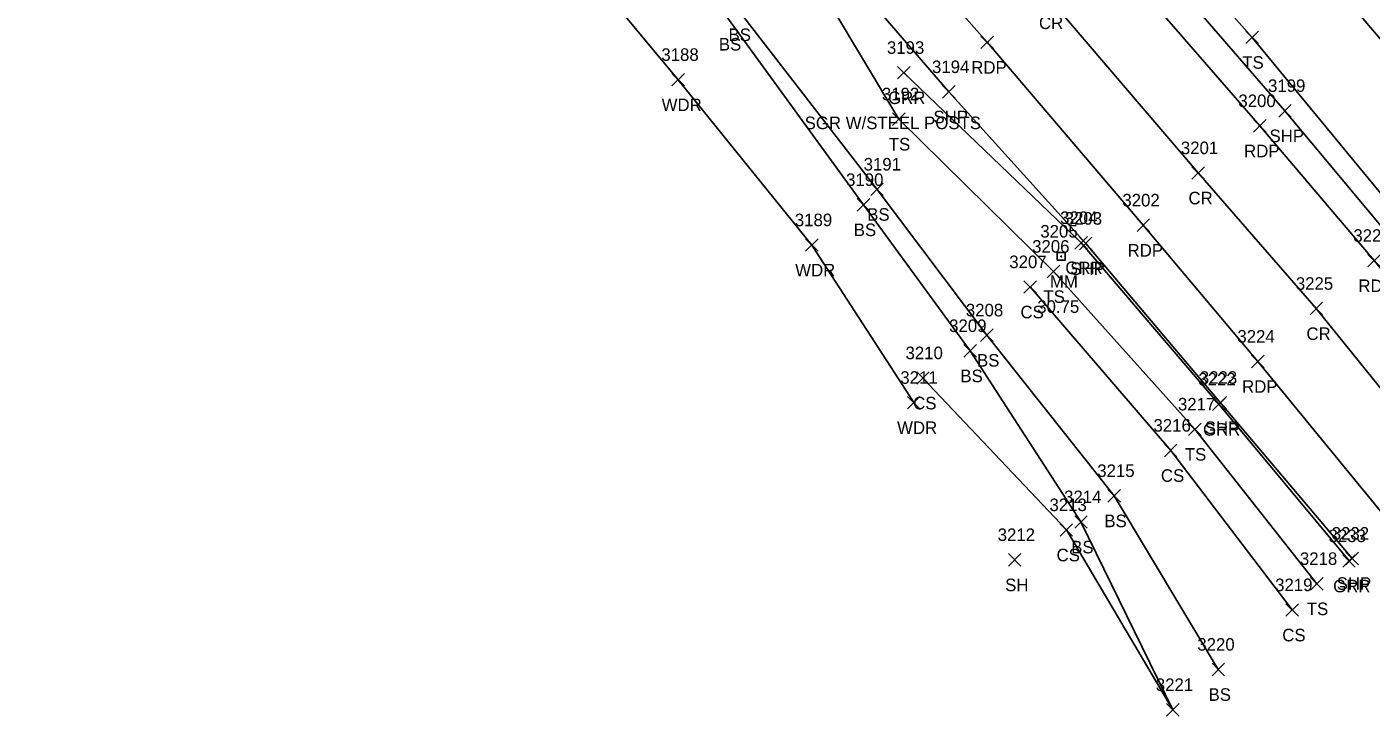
# Model space of a CAD drawing. Extents: x 1647574 to 1652703, y 212895 to 228670.
# Drawn here: x 1649906.5 to 1650120.6, y 225938.9 to 226048.7 of the extents above; entities that cross this region are included whole.
import ezdxf

# ---------------------------------------------------------------- set-up
doc = ezdxf.new("R2010")
doc.units = 0
for name, color, linetype in [('L_A', 7, 'Continuous'), ('L_I', 7, 'Continuous'), ('L_TIC', 7, 'Continuous'), ('LAWA', 7, 'Continuous'), ('LELB', 7, 'Continuous'), ('P_A', 7, 'Continuous'), ('P_I', 7, 'Continuous'), ('P_TIC', 7, 'Continuous'), ('PET', 7, 'Continuous'), ('PRC', 7, 'Continuous'), ('PSP', 7, 'Continuous'), ('R_A', 7, 'Continuous'), ('R_C', 7, 'Continuous'), ('R_I', 7, 'Continuous'), ('R_TIC', 7, 'Continuous'), ('RGR', 7, 'Continuous'), ('S_A', 7, 'Continuous'), ('S_C', 7, 'Continuous'), ('S_I', 7, 'Continuous'), ('SRM', 7, 'Continuous')]:
    doc.layers.add(name, color=color, linetype=linetype)

msp = doc.modelspace()

# ---------------------------------------------------------------- linework, layer by layer
at = {"layer": 'L_TIC'}
for points in [[(1650100.66, 226046.08), (1650102.66, 226048.08)], [(1650102.66, 226046.08), (1650100.66, 226048.08)], [(1650009.23, 226039.33), (1650011.23, 226041.33)], [(1650011.23, 226039.33), (1650009.23, 226041.33)], [(1650044.36, 226033.05), (1650046.36, 226035.05)], [(1650046.36, 226033.05), (1650044.36, 226035.05)], [(1650040.89, 226021.86), (1650042.89, 226023.86)], [(1650042.89, 226021.86), (1650040.89, 226023.86)], [(1650038.74, 226019.41), (1650040.74, 226021.41)], [(1650040.74, 226019.41), (1650038.74, 226021.41)], [(1650030.5, 226012.99), (1650032.5, 226014.99)], [(1650032.5, 226012.99), (1650030.5, 226014.99)], [(1650068.99, 226008.77), (1650070.99, 226010.77)], [(1650070.99, 226008.77), (1650068.99, 226010.77)], [(1650065.29, 226006.31), (1650067.29, 226008.31)], [(1650067.29, 226006.31), (1650065.29, 226008.31)], [(1650058.37, 225998.62), (1650060.37, 226000.62)], [(1650060.37, 225998.62), (1650058.37, 226000.62)], [(1650055.73, 225996.13), (1650057.73, 225998.13)], [(1650057.73, 225996.13), (1650055.73, 225998.13)], [(1650048.21, 225991.8), (1650050.21, 225993.8)], [(1650050.21, 225991.8), (1650048.21, 225993.8)], [(1650046.73, 225987.88), (1650048.73, 225989.88)], [(1650048.73, 225987.88), (1650046.73, 225989.88)], [(1650091.51, 225983.63), (1650093.51, 225985.63)], [(1650093.51, 225983.63), (1650091.51, 225985.63)], [(1650087.67, 225980.26), (1650089.67, 225982.26)], [(1650089.67, 225980.26), (1650087.67, 225982.26)], [(1650078.66, 225973.03), (1650080.66, 225975.03)], [(1650080.66, 225973.03), (1650078.66, 225975.03)], [(1650071.05, 225967.59), (1650073.05, 225969.59)], [(1650073.05, 225967.59), (1650071.05, 225969.59)], [(1650073.38, 225968.86), (1650075.38, 225970.86)], [(1650075.38, 225968.86), (1650073.38, 225970.86)], [(1650062.81, 225962.83), (1650064.81, 225964.83)], [(1650064.81, 225962.83), (1650062.81, 225964.83)], [(1650110.94, 225959.02), (1650112.94, 225961.02)], [(1650112.94, 225959.02), (1650110.94, 225961.02)], [(1650107, 225954.84), (1650109, 225956.84)], [(1650109, 225954.84), (1650107, 225956.84)], [(1650095.25, 225945.36), (1650097.25, 225947.36)], [(1650097.25, 225945.36), (1650095.25, 225947.36)], [(1650088, 225938.93), (1650090, 225940.93)], [(1650090, 225938.93), (1650088, 225940.93)], [(1650088, 225938.93), (1650090, 225940.93)], [(1650090, 225938.93), (1650088, 225940.93)]]:
    msp.add_lwpolyline(points, dxfattribs=at)
at = {"layer": 'LAWA'}
msp.add_lwpolyline([(1649564.01, 226501.21), (1649600.78, 226471.1), (1649629.15, 226441.1), (1649657.11, 226422.45), (1649662.3, 226420.26), (1649668.81, 226414.71), (1649676.02, 226404.08), (1649707.48, 226367.52), (1649746.55, 226330.39), (1649779.45, 226297), (1649815.18, 226260.26), (1649850.99, 226223.94), (1649889.13, 226181.22), (1649919.64, 226149.68), (1649954.03, 226112.54), (1649976.77, 226080.57), (1650010.23, 226040.33), (1650031.5, 226013.99), (1650047.73, 225988.88)], dxfattribs=at)
at = {"layer": 'LELB'}
for points in [[(1650145.31, 225996.12), (1650126.11, 226017.39), (1650101.66, 226047.08), (1650074.02, 226078.27), (1650048.35, 226107.52), (1650011.02, 226148.89), (1649978.29, 226184.76), (1649948.32, 226216.56), (1649918.31, 226248.62), (1649881.09, 226286.67), (1649854.51, 226315.1), (1649822.53, 226345.57), (1649790.94, 226377.4), (1649759.46, 226406.66), (1649722.98, 226440.72), (1649699.36, 226464.18), (1649670.41, 226492.35), (1649633.05, 226526.99), (1649601.72, 226556.3), (1649565.56, 226590.44)], [(1649576.43, 226518.4), (1649614.41, 226482.98), (1649642.41, 226455.9), (1649685.38, 226415.67), (1649721.92, 226380.74), (1649759.16, 226344.82), (1649794.41, 226310.27), (1649829.09, 226276.12), (1649866.9, 226238.21), (1649900.81, 226202.84), (1649937.1, 226163.93), (1649969.44, 226128.19), (1649998.01, 226097.17), (1650029.45, 226060.68), (1650045.36, 226034.05), (1650069.99, 226009.77), (1650092.51, 225984.63), (1650111.94, 225960.02)], [(1649570.19, 226510.51), (1649608.23, 226476.35), (1649636.57, 226449.06), (1649663.19, 226421.28), (1649670.48, 226414.78), (1649679.22, 226408.18), (1649715.79, 226375.57), (1649754.34, 226338.61), (1649788.1, 226305.21), (1649822.67, 226268.96), (1649860.5, 226231.77), (1649895.97, 226193.57), (1649929.13, 226157.26), (1649962.02, 226120.66), (1649988.9, 226089.08), (1650019.8, 226051.49), (1650041.89, 226022.86), (1650059.37, 225999.62), (1650079.66, 225974.03), (1650096.25, 225946.36)], [(1650148.97, 226010.88), (1650139.27, 226026.59), (1650113.43, 226057), (1650088.3, 226087.98), (1650061.28, 226120.08), (1650026.24, 226159.75), (1649992.44, 226196.13), (1649963.33, 226228.07), (1649931.94, 226262.56), (1649896.29, 226297.95), (1649867.38, 226328.16), (1649836.11, 226358.29), (1649802.88, 226390.85), (1649773.49, 226418.93), (1649757.57, 226433.02), (1649733.38, 226449.67), (1649721.38, 226464.7), (1649717.89, 226468.09), (1649721.1, 226472.27), (1649725.43, 226467.47)], [(1649668.81, 226414.71), (1649677.68, 226406.85), (1649713.8, 226373.3), (1649752.12, 226335.89), (1649786.09, 226302.81), (1649821.42, 226267.05), (1649857.98, 226229.57), (1649894.19, 226191.19), (1649927.6, 226155.83), (1649960.21, 226119.33), (1649987.22, 226087.32), (1650018.26, 226049.98), (1650039.74, 226020.41), (1650056.73, 225997.13), (1650074.38, 225969.86), (1650089, 225939.93)], [(1650066.29, 226007.31), (1650088.67, 225981.26), (1650108, 225955.84)], [(1650049.21, 225992.8), (1650072.05, 225968.59), (1650089, 225939.93)]]:
    msp.add_lwpolyline(points, dxfattribs=at)
at = {"layer": 'P_TIC'}
for points in [[(1650058.42, 226045.29), (1650060.42, 226047.29)], [(1650060.42, 226045.29), (1650058.42, 226047.29)], [(1650052.34, 226037.39), (1650054.34, 226039.39)], [(1650054.34, 226037.39), (1650052.34, 226039.39)], [(1650105.87, 226034.38), (1650107.87, 226036.38)], [(1650107.87, 226034.38), (1650105.87, 226036.38)], [(1650101.87, 226031.97), (1650103.87, 226033.97)], [(1650103.87, 226031.97), (1650101.87, 226033.97)], [(1650092.06, 226024.47), (1650094.06, 226026.47)], [(1650094.06, 226024.47), (1650092.06, 226026.47)], [(1650083.31, 226016.14), (1650085.31, 226018.14)], [(1650085.31, 226016.14), (1650083.31, 226018.14)], [(1650074.13, 226013.23), (1650076.13, 226015.23)], [(1650076.13, 226013.23), (1650074.13, 226015.23)], [(1650120.07, 226010.5), (1650122.07, 226012.5)], [(1650122.07, 226010.5), (1650120.07, 226012.5)], [(1650110.86, 226002.86), (1650112.86, 226004.86)], [(1650112.86, 226002.86), (1650110.86, 226004.86)], [(1650101.55, 225994.44), (1650103.55, 225996.44)], [(1650103.55, 225994.44), (1650101.55, 225996.44)], [(1650095.57, 225987.88), (1650097.57, 225989.88)], [(1650097.57, 225987.88), (1650095.57, 225989.88)], [(1650116.58, 225963.05), (1650118.58, 225965.05)], [(1650118.58, 225963.05), (1650116.58, 225965.05)]]:
    msp.add_lwpolyline(points, dxfattribs=at)
at = {"layer": 'PET'}
for points in [[(1649568.76, 226578.15), (1649602.84, 226545.72), (1649639.6, 226511.14), (1649669.58, 226482.71), (1649710.56, 226443.02), (1649749.16, 226406.1), (1649783.82, 226372.91), (1649821.53, 226335.91), (1649854.36, 226303.39), (1649893.84, 226262.84), (1649926.53, 226228.81), (1649964.59, 226188.34), (1649995.88, 226154.08), (1650026.58, 226120.39), (1650056.63, 226086.43), (1650078.17, 226061.47), (1650102.87, 226032.97), (1650121.07, 226011.5), (1650140.46, 225987.82)], [(1649585.69, 226528.77), (1649624.3, 226492.34), (1649652.1, 226465.47), (1649694.18, 226424.93), (1649731.2, 226389.82), (1649767.06, 226355.29), (1649804.34, 226318.78), (1649837.23, 226285.73), (1649875.09, 226247.37), (1649909.48, 226211.77), (1649946.37, 226172.47), (1649978.25, 226137.54), (1650007.65, 226104.95), (1650038.73, 226069.71), (1650059.42, 226046.29), (1650084.31, 226017.14), (1650102.55, 225995.44), (1650123.3, 225970.1)]]:
    msp.add_lwpolyline(points, dxfattribs=at)
at = {"layer": 'PRC'}
msp.add_lwpolyline([(1649559.91, 226569.96), (1649593.92, 226537.25), (1649631.94, 226502.23), (1649660.46, 226474.34), (1649702.15, 226434.36), (1649740.4, 226397.48), (1649775.04, 226364.12), (1649813.32, 226327.22), (1649846.03, 226294.55), (1649884.93, 226255.04), (1649918.06, 226220.06), (1649955.14, 226180.9), (1649987.04, 226146.06), (1650016.78, 226113.16), (1650047.62, 226077.89), (1650069.26, 226053.4), (1650093.06, 226025.47), (1650111.86, 226003.86), (1650131.21, 225979.86)], dxfattribs=at)
at = {"layer": 'PSP'}
for points in [[(1649571.18, 226581.28), (1649605.62, 226548.46), (1649642.47, 226514.36), (1649673.51, 226485.11), (1649713.05, 226446.56), (1649753.13, 226408.58), (1649786.75, 226376.31), (1649825.02, 226339.17), (1649858.01, 226306.81), (1649897.5, 226266.11), (1649930.08, 226232.3), (1649968.22, 226191.53), (1649999.65, 226157.4), (1650029.99, 226123.79), (1650060.42, 226089.05), (1650081.82, 226064.3), (1650106.87, 226035.38), (1650124.34, 226014.45), (1650143.68, 225990.93)], [(1649578.75, 226520.79), (1649616.88, 226484.95), (1649644.67, 226458.4), (1649687.66, 226417.66), (1649724.18, 226382.77), (1649761.14, 226347.64), (1649797.11, 226312.71), (1649831.3, 226278.59), (1649868.9, 226240.31), (1649902.65, 226204.83), (1649939.09, 226165.73), (1649971.52, 226130.61), (1650000.21, 226098.9), (1650032.08, 226063.05), (1650053.34, 226038.39), (1650075.13, 226014.23), (1650096.57, 225988.88), (1650117.58, 225964.05)]]:
    msp.add_lwpolyline(points, dxfattribs=at)
at = {"layer": 'R_TIC'}
for points in [[(1650045.16, 226040.45), (1650047.16, 226042.45)], [(1650047.16, 226040.45), (1650045.16, 226042.45)], [(1650073.4, 226013.35), (1650075.4, 226015.35)], [(1650075.4, 226013.35), (1650073.4, 226015.35)], [(1650095.33, 225987.61), (1650097.33, 225989.61)], [(1650097.33, 225987.61), (1650095.33, 225989.61)], [(1650116.07, 225962.65), (1650118.07, 225964.65)], [(1650118.07, 225962.65), (1650116.07, 225964.65)]]:
    msp.add_lwpolyline(points, dxfattribs=at)
at = {"layer": 'RGR'}
msp.add_lwpolyline([(1650046.16, 226041.45), (1650074.4, 226014.35), (1650096.33, 225988.61), (1650117.07, 225963.65)], dxfattribs=at)
at = {"layer": 'SRM'}
msp.add_lwpolyline([(1650070.61, 226012.8), (1650071.86, 226012.8), (1650071.86, 226011.55), (1650070.61, 226011.55)], close=True, dxfattribs=at)
msp.add_circle((1650071.24, 226012.18), 0.0833, dxfattribs=at)

# ---------------------------------------------------------------- texts
at = {"layer": 'L_A'}
for s, p in [('BS', (1650016.7, 226044.98)), ('BS', (1650018.24, 226046.49)), ('TS', (1650100.07, 226042.08)), ('WDR', (1650007.59, 226035.33)), ('TS', (1650043.77, 226029.05)), ('BS', (1650040.33, 226017.86)), ('BS', (1650038.19, 226015.41)), ('WDR', (1650028.86, 226008.99)), ('TS', (1650068.4, 226004.77)), ('CS', (1650064.74, 226002.31)), ('BS', (1650057.82, 225994.62)), ('BS', (1650055.17, 225992.13)), ('CS', (1650047.65, 225987.8)), ('WDR', (1650045.09, 225983.88)), ('TS', (1650090.92, 225979.63)), ('CS', (1650087.11, 225976.26)), ('BS', (1650078.1, 225969.03)), ('CS', (1650070.49, 225963.59)), ('BS', (1650072.82, 225964.86)), ('SH', (1650062.3, 225958.83)), ('TS', (1650110.35, 225955.02)), ('CS', (1650106.44, 225950.84)), ('BS', (1650094.7, 225941.36))]:
    msp.add_text(s, height=2, dxfattribs=at).set_placement(p)
at = {"layer": 'L_I'}
for s, p in [('3188', (1650007.54, 226043.33)), ('3192', (1650042.67, 226037.05)), ('3191', (1650039.76, 226025.86)), ('3190', (1650036.96, 226023.41)), ('3189', (1650028.8, 226016.99)), ('3206', (1650066.6, 226012.77)), ('3207', (1650062.96, 226010.31)), ('3208', (1650056.04, 226002.62)), ('3209', (1650053.38, 226000.13)), ('3210', (1650046.43, 225995.8)), ('3211', (1650045.6, 225991.88)), ('3217', (1650089.82, 225987.63)), ('3216', (1650085.93, 225984.26)), ('3215', (1650076.97, 225977.03)), ('3213', (1650069.36, 225971.59)), ('3214', (1650071.69, 225972.86)), ('3212', (1650061.11, 225966.83)), ('3218', (1650109.25, 225963.02)), ('3219', (1650105.3, 225958.84)), ('3220', (1650092.91, 225949.36)), ('3221', (1650086.3, 225942.93)), ('3221', (1650086.3, 225942.93))]:
    msp.add_text(s, height=2, dxfattribs=at).set_placement(p)
at = {"layer": 'P_A'}
for s, p in [('CR', (1650067.69, 226048.4)), ('RDP', (1650056.9, 226041.29)), ('SHP', (1650050.88, 226033.39)), ('SHP', (1650104.41, 226030.38)), ('RDP', (1650100.36, 226027.97)), ('CR', (1650091.5, 226020.47)), ('RDP', (1650081.8, 226012.14)), ('SHP', (1650072.67, 226009.23)), ('RDP', (1650118.56, 226006.5)), ('CR', (1650110.29, 225998.86)), ('RDP', (1650100.04, 225990.44)), ('SHP', (1650094.1, 225983.88)), ('SHP', (1650115.11, 225959.05))]:
    msp.add_text(s, height=2, dxfattribs=at).set_placement(p)
at = {"layer": 'P_I'}
for s, p in [('3194', (1650050.65, 226041.39)), ('3199', (1650104.17, 226038.38)), ('3200', (1650099.45, 226035.97)), ('3201', (1650090.29, 226028.47)), ('3202', (1650080.97, 226020.14)), ('3203', (1650071.79, 226017.23)), ('3226', (1650117.76, 226014.5)), ('3225', (1650108.6, 226006.86)), ('3224', (1650099.29, 225998.44)), ('3223', (1650093.31, 225991.88)), ('3232', (1650114.32, 225967.05))]:
    msp.add_text(s, height=2, dxfattribs=at).set_placement(p)
at = {"layer": 'R_A'}
for p in [(1650043.65, 226036.45), (1650071.89, 226009.35), (1650093.82, 225983.61), (1650114.55, 225958.65)]:
    msp.add_text('GRR', height=2, dxfattribs=at).set_placement(p)
at = {"layer": 'R_C'}
msp.add_text('SGR W/STEEL POSTS', height=2, dxfattribs=at).set_placement((1650030.37, 226032.45))
at = {"layer": 'R_I'}
for s, p in [('3193', (1650043.47, 226044.45)), ('3204', (1650071.06, 226017.35)), ('3222', (1650093.07, 225991.61)), ('3233', (1650113.81, 225966.65))]:
    msp.add_text(s, height=2, dxfattribs=at).set_placement(p)
at = {"layer": 'S_A'}
msp.add_text('MM', height=2, dxfattribs=at).set_placement((1650069.43, 226007.18))
at = {"layer": 'S_C'}
msp.add_text('30.75', height=2, dxfattribs=at).set_placement((1650067.41, 226003.18))
at = {"layer": 'S_I'}
msp.add_text('3205', height=2, dxfattribs=at).set_placement((1650067.9, 226015.18))

doc.saveas('drawing.dxf')
